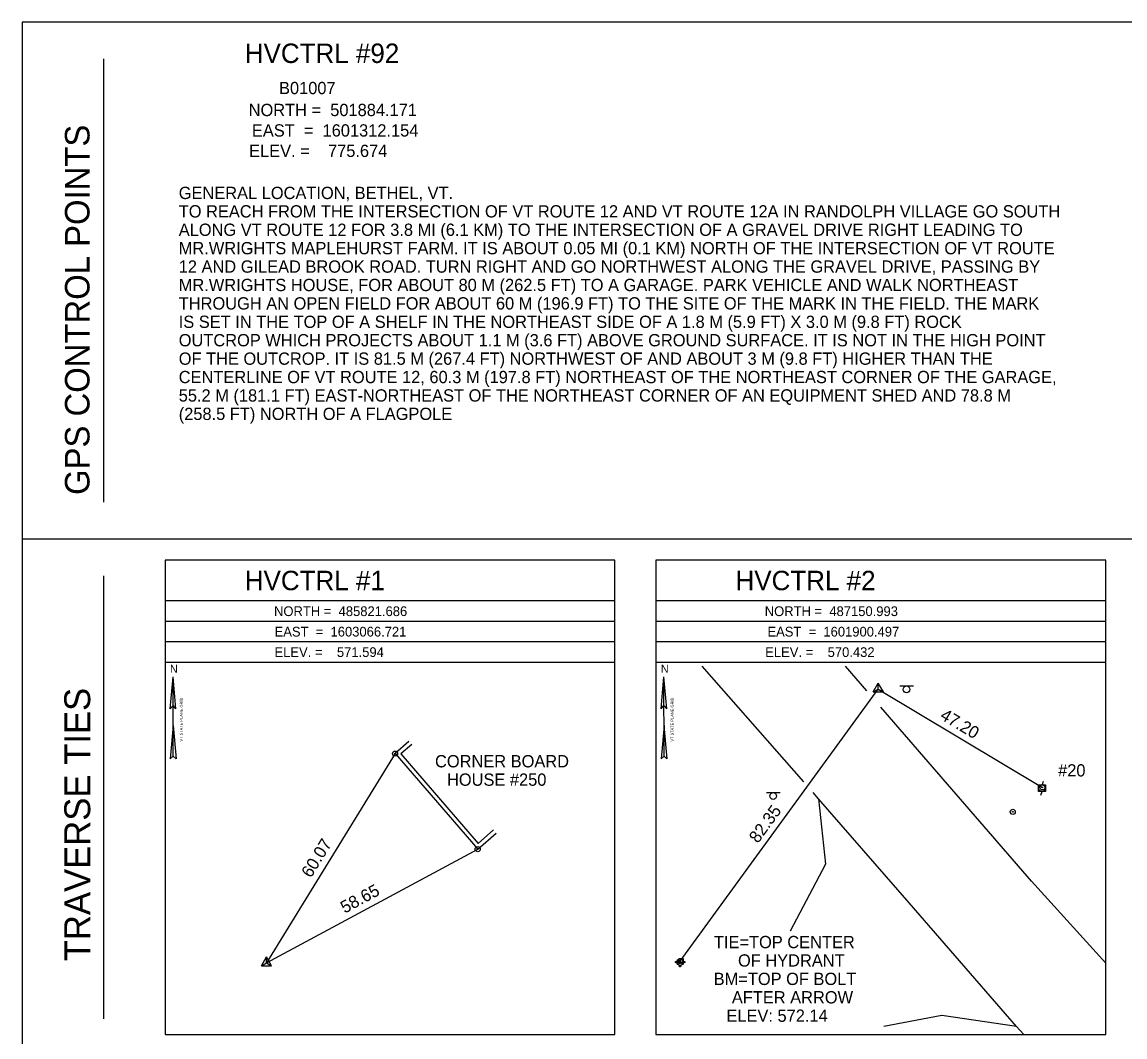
# Model space of a CAD drawing. Extents: x 1598730 to 1599370, y 501440 to 502728.
# Drawn here: x 1598729.5 to 1598999.2, y 502479.8 to 502727.8 of the extents above; entities that cross this region are included whole.
import ezdxf

# ---------------------------------------------------------------- set-up
doc = ezdxf.new("R2010")
doc.units = 0
for name, color, linetype in [('C_C', 7, 'Continuous'), ('CBP', 7, 'Continuous'), ('CPBM', 7, 'Continuous'), ('CPSM', 7, 'Continuous'), ('Default', 7, 'Continuous'), ('LBC', 7, 'Continuous'), ('NBL1', 7, 'Continuous'), ('NBL2', 7, 'Continuous'), ('NNA_P', 7, 'Continuous'), ('PET', 7, 'Continuous'), ('RDP', 7, 'Continuous'), ('SSGN', 7, 'Continuous'), ('U_C', 7, 'Continuous'), ('UP', 7, 'Continuous'), ('UPGW', 7, 'Continuous'), ('UWFH', 7, 'Continuous')]:
    doc.layers.add(name, color=color, linetype=linetype)

msp = doc.modelspace()

# ---------------------------------------------------------------- linework, layer by layer
at = {"layer": 'CBP'}
for centre, radius in [((1598820.74, 502549.03), 0.625), ((1598820.74, 502549.03), 0.0833), ((1598979.04, 502540.77), 0.625), ((1598979.04, 502540.77), 0.0833), ((1598840.95, 502525.67), 0.625), ((1598840.95, 502525.67), 0.0833), ((1598890.48, 502498.27), 0.625), ((1598890.48, 502498.27), 0.0833)]:
    msp.add_circle(centre, radius, dxfattribs=at)
at = {"layer": 'CPBM'}
for p, q in [((1598890.22, 502497.95), (1598890.22, 502498.95)), ((1598890.22, 502498.95), (1598891.22, 502498.95)), ((1598890.72, 502498.45), (1598890.72, 502498.45)), ((1598890.72, 502498.45), (1598890.72, 502498.45)), ((1598891.22, 502498.95), (1598891.22, 502497.95)), ((1598891.22, 502497.95), (1598890.22, 502497.95))]:
    msp.add_line(p, q, dxfattribs=at)
at = {"layer": 'CPSM'}
for p, q in [((1598937.65, 502564.09), (1598938.9, 502566.25)), ((1598940.15, 502564.09), (1598938.9, 502566.25)), ((1598938.9, 502564.81), (1598938.9, 502566.25)), ((1598937.65, 502564.09), (1598938.9, 502564.81)), ((1598937.65, 502564.09), (1598940.15, 502564.09)), ((1598938.9, 502564.81), (1598938.9, 502564.81)), ((1598938.9, 502564.81), (1598940.15, 502564.09)), ((1598788.05, 502497.17), (1598789.3, 502499.33)), ((1598790.55, 502497.17), (1598789.3, 502499.33)), ((1598789.3, 502497.89), (1598789.3, 502499.33)), ((1598788.05, 502497.17), (1598789.3, 502497.89)), ((1598788.05, 502497.17), (1598790.55, 502497.17)), ((1598789.3, 502497.89), (1598789.3, 502497.89)), ((1598789.3, 502497.89), (1598790.55, 502497.17))]:
    msp.add_line(p, q, dxfattribs=at)
at = {"layer": 'Default'}
for p, q in [((1598890.48, 502498.27), (1598938.9, 502564.81)), ((1598938.9, 502564.81), (1598979.04, 502540.77)), ((1598820.74, 502549.03), (1598789.3, 502497.89)), ((1598789.3, 502497.89), (1598840.95, 502525.67))]:
    msp.add_line(p, q, dxfattribs=at)
at = {"layer": 'LBC'}
for p, q in [((1598824.15, 502551.99), (1598820.74, 502549.03)), ((1598820.74, 502549.03), (1598840.95, 502525.67)), ((1598840.95, 502525.67), (1598845.51, 502529.61))]:
    msp.add_line(p, q, dxfattribs=at)
msp.add_lwpolyline([(1598824.81, 502551.23), (1598822.15, 502548.93), (1598841.05, 502527.08), (1598844.85, 502530.37)], dxfattribs=at)
at = {"layer": 'NBL1'}
msp.add_lwpolyline([(1598729.53, 502307.83), (1599369.53, 502307.83), (1599369.53, 502727.83), (1598729.53, 502727.83)], close=True, dxfattribs=at)
at = {"layer": 'NBL2'}
for p, q in [((1598749.53, 502610.5), (1598749.53, 502718.83)), ((1598729.53, 502601.5), (1599369.53, 502601.5)), ((1598749.53, 502484.17), (1598749.53, 502592.5)), ((1598874.53, 502586.33), (1598764.53, 502586.33)), ((1598994.53, 502586.33), (1598884.53, 502586.33)), ((1598874.53, 502581.33), (1598764.53, 502581.33)), ((1598994.53, 502581.33), (1598884.53, 502581.33)), ((1598874.53, 502576.33), (1598764.53, 502576.33)), ((1598994.53, 502576.33), (1598884.53, 502576.33)), ((1598874.53, 502571.33), (1598764.53, 502571.33)), ((1598994.53, 502571.33), (1598884.53, 502571.33))]:
    msp.add_line(p, q, dxfattribs=at)
for points in [[(1598764.53, 502480.33), (1598874.53, 502480.33), (1598874.53, 502596.33), (1598764.53, 502596.33)], [(1598884.53, 502480.33), (1598994.53, 502480.33), (1598994.53, 502596.33), (1598884.53, 502596.33)]]:
    msp.add_lwpolyline(points, close=True, dxfattribs=at)
at = {"layer": 'NNA_P'}
for p, q in [((1598765.77, 502559.98), (1598766.46, 502567.77)), ((1598766.46, 502548.4), (1598766.46, 502567.77)), ((1598767.15, 502559.98), (1598766.46, 502567.77)), ((1598885.82, 502559.98), (1598886.51, 502567.77)), ((1598886.52, 502548.4), (1598886.51, 502567.77)), ((1598887.21, 502559.98), (1598886.51, 502567.77)), ((1598765.77, 502559.98), (1598766.46, 502560.75)), ((1598767.16, 502559.98), (1598766.46, 502560.75)), ((1598885.82, 502559.98), (1598886.51, 502560.75)), ((1598887.21, 502559.98), (1598886.51, 502560.75)), ((1598766.47, 502555.92), (1598765.74, 502547.76)), ((1598766.46, 502555.92), (1598767.19, 502547.76)), ((1598886.52, 502555.92), (1598885.8, 502547.76)), ((1598886.51, 502555.92), (1598887.24, 502547.76)), ((1598766.46, 502548.4), (1598765.74, 502547.76)), ((1598766.46, 502548.4), (1598767.19, 502547.76)), ((1598886.52, 502548.4), (1598885.8, 502547.76)), ((1598886.52, 502548.4), (1598887.24, 502547.76))]:
    msp.add_line(p, q, dxfattribs=at)
at = {"layer": 'PET'}
for points in [[(1598920.7, 502542.1), (1598895.88, 502570.42)], [(1598936.12, 502564.36), (1598930.87, 502570.42)], [(1598994.58, 502497.81), (1598976.34, 502517.87), (1598939.56, 502560.38)], [(1598974.4, 502480.46), (1598972.7, 502482.3), (1598946.48, 502512.52), (1598924.32, 502537.96), (1598922.95, 502539.53)]]:
    msp.add_lwpolyline(points, dxfattribs=at)
at = {"layer": 'RDP'}
for points in [[(1598924.32, 502537.96), (1598926, 502521.99), (1598917.38, 502505.58)], [(1598972.7, 502482.3), (1598954.44, 502485.01), (1598940.31, 502482.33)]]:
    msp.add_lwpolyline(points, dxfattribs=at)
at = {"layer": 'SSGN'}
for p, q in [((1598944.16, 502565.56), (1598947.5, 502565.56)), ((1598945.81, 502564.73), (1598945.81, 502564.73)), ((1598911.56, 502539.49), (1598914.9, 502539.49)), ((1598913.21, 502538.66), (1598913.21, 502538.66))]:
    msp.add_line(p, q, dxfattribs=at)
for centre in [(1598945.81, 502564.73), (1598913.21, 502538.66)]:
    msp.add_circle(centre, 0.833, dxfattribs=at)
at = {"layer": 'UP'}
for p, q in [((1598978.12, 502539.73), (1598978.12, 502541.4)), ((1598978.12, 502541.4), (1598979.79, 502541.4)), ((1598979.2, 502542.23), (1598978.95, 502541.4)), ((1598979.79, 502541.4), (1598979.79, 502539.73)), ((1598979.79, 502539.73), (1598978.12, 502539.73)), ((1598978.7, 502538.9), (1598978.95, 502539.73)), ((1598978.95, 502540.56), (1598978.95, 502540.56))]:
    msp.add_line(p, q, dxfattribs=at)
msp.add_circle((1598978.95, 502540.56), 0.833, dxfattribs=at)
at = {"layer": 'UPGW'}
for radius in [0.625, 0.0833]:
    msp.add_circle((1598971.8, 502534.78), radius, dxfattribs=at)
at = {"layer": 'UWFH'}
msp.add_line((1598890.46, 502498.05), (1598890.46, 502498.05), dxfattribs=at)
for centre, radius in [((1598889.46, 502498.05), 0.167), ((1598890.46, 502498.05), 0.833), ((1598891.46, 502498.05), 0.167), ((1598890.46, 502497.05), 0.167)]:
    msp.add_circle(centre, radius, dxfattribs=at)

# ---------------------------------------------------------------- texts
at = {"layer": 'C_C'}
for s, p in [('CORNER BOARD', (1598830.52, 502545.66)), ('HOUSE #250', (1598833.45, 502541.16)), ('TIE=TOP CENTER', (1598898.72, 502501.46)), ('OF HYDRANT', (1598904.61, 502496.96)), ('BM=TOP OF BOLT', (1598898.66, 502492.46)), ('AFTER ARROW', (1598903.11, 502487.96)), ('ELEV: 572.14', (1598901.78, 502483.46))]:
    msp.add_text(s, height=3, dxfattribs=at).set_placement(p)
at = {"layer": 'Default'}
for s, p in [('GENERAL LOCATION, BETHEL, VT. ', (1598767.85, 502684.57)), ('TO REACH FROM THE INTERSECTION OF VT ROUTE 12 AND VT ROUTE 12A IN RANDOLPH VILLAGE GO SOUTH ', (1598767.85, 502680.07)), ('ALONG VT ROUTE 12 FOR 3.8 MI (6.1 KM) TO THE INTERSECTION OF A GRAVEL DRIVE RIGHT LEADING TO ', (1598767.85, 502675.57)), ('MR.WRIGHTS MAPLEHURST FARM. IT IS ABOUT 0.05 MI (0.1 KM) NORTH OF THE INTERSECTION OF VT ROUTE ', (1598767.85, 502671.07)), ('12 AND GILEAD BROOK ROAD. TURN RIGHT AND GO NORTHWEST ALONG THE GRAVEL DRIVE, PASSING BY ', (1598767.85, 502666.57)), ('MR.WRIGHTS HOUSE, FOR ABOUT 80 M (262.5 FT) TO A GARAGE. PARK VEHICLE AND WALK NORTHEAST ', (1598767.85, 502662.07)), ('THROUGH AN OPEN FIELD FOR ABOUT 60 M (196.9 FT) TO THE SITE OF THE MARK IN THE FIELD. THE MARK ', (1598767.85, 502657.57)), ('IS SET IN THE TOP OF A SHELF IN THE NORTHEAST SIDE OF A 1.8 M (5.9 FT) X 3.0 M (9.8 FT) ROCK ', (1598767.85, 502653.07)), ('OUTCROP WHICH PROJECTS ABOUT 1.1 M (3.6 FT) ABOVE GROUND SURFACE. IT IS NOT IN THE HIGH POINT ', (1598767.85, 502648.57)), ('OF THE OUTCROP. IT IS 81.5 M (267.4 FT) NORTHWEST OF AND ABOUT 3 M (9.8 FT) HIGHER THAN THE ', (1598767.85, 502644.07)), ('CENTERLINE OF VT ROUTE 12, 60.3 M (197.8 FT) NORTHEAST OF THE NORTHEAST CORNER OF THE GARAGE, ', (1598767.85, 502639.57)), ('55.2 M (181.1 FT) EAST-NORTHEAST OF THE NORTHEAST CORNER OF AN EQUIPMENT SHED AND 78.8 M ', (1598767.85, 502635.07)), ('(258.5 FT) NORTH OF A FLAGPOLE', (1598767.85, 502630.57))]:
    msp.add_text(s, height=3, dxfattribs=at).set_placement(p)
for s, rotation, p in [('47.20', 329.0802, (1598953.8, 502557.63)), ('82.35', 53.9596, (1598909.48, 502526.93)), ('60.07', 58.4216, (1598800.18, 502518.46)), ('58.65', 28.2747, (1598808.43, 502509.88))]:
    msp.add_text(s, height=3, rotation=rotation, dxfattribs=at).set_placement(p)
at = {"layer": 'NBL2'}
for s, height, p in [('     HVCTRL #92    ', 4.75, (1598775.18, 502717.83)), ('        B01007       ', 3, (1598783.46, 502710.21)), ('NORTH =  501884.171 ', 3, (1598784.95, 502704.85)), ('EAST  =  1601312.154', 3, (1598785.74, 502699.85)), ('ELEV. =    775.674  ', 3, (1598785.06, 502694.85)), ('     HVCTRL #1     ', 4.75, (1598775.18, 502588.96)), ('     HVCTRL #2     ', 4.75, (1598895.18, 502588.96)), ('NORTH =  485821.686 ', 2.375, (1598791.15, 502582.64)), ('NORTH =  487150.993 ', 2.375, (1598911.15, 502582.64)), ('EAST  =  1603066.721', 2.375, (1598791.29, 502577.64)), ('EAST  =  1601900.497', 2.375, (1598911.81, 502577.64)), ('ELEV. =    571.594  ', 2.375, (1598791.26, 502572.64)), ('ELEV. =    570.432  ', 2.375, (1598911.26, 502572.64))]:
    msp.add_text(s, height=height, dxfattribs=at).set_placement(p)
for s, height, p in [('GPS CONTROL POINTS', 6, (1598746.03, 502612.25)), ('TRAVERSE TIES', 6.3332, (1598746.2, 502498.27))]:
    msp.add_text(s, height=height, rotation=90, dxfattribs=at).set_placement(p)
at = {"layer": 'NNA_P'}
for p in [(1598765.7, 502568.78), (1598885.75, 502568.78)]:
    msp.add_text('N', height=1.97, dxfattribs=at).set_placement(p)
for p in [(1598768.82, 502551.96), (1598888.87, 502551.96)]:
    msp.add_text('VT STATE PLANE GRID', height=0.7, rotation=90.0204, dxfattribs=at).set_placement(p)
at = {"layer": 'U_C'}
msp.add_text('#20', height=3, dxfattribs=at).set_placement((1598982.89, 502543.43))

doc.saveas('drawing.dxf')
